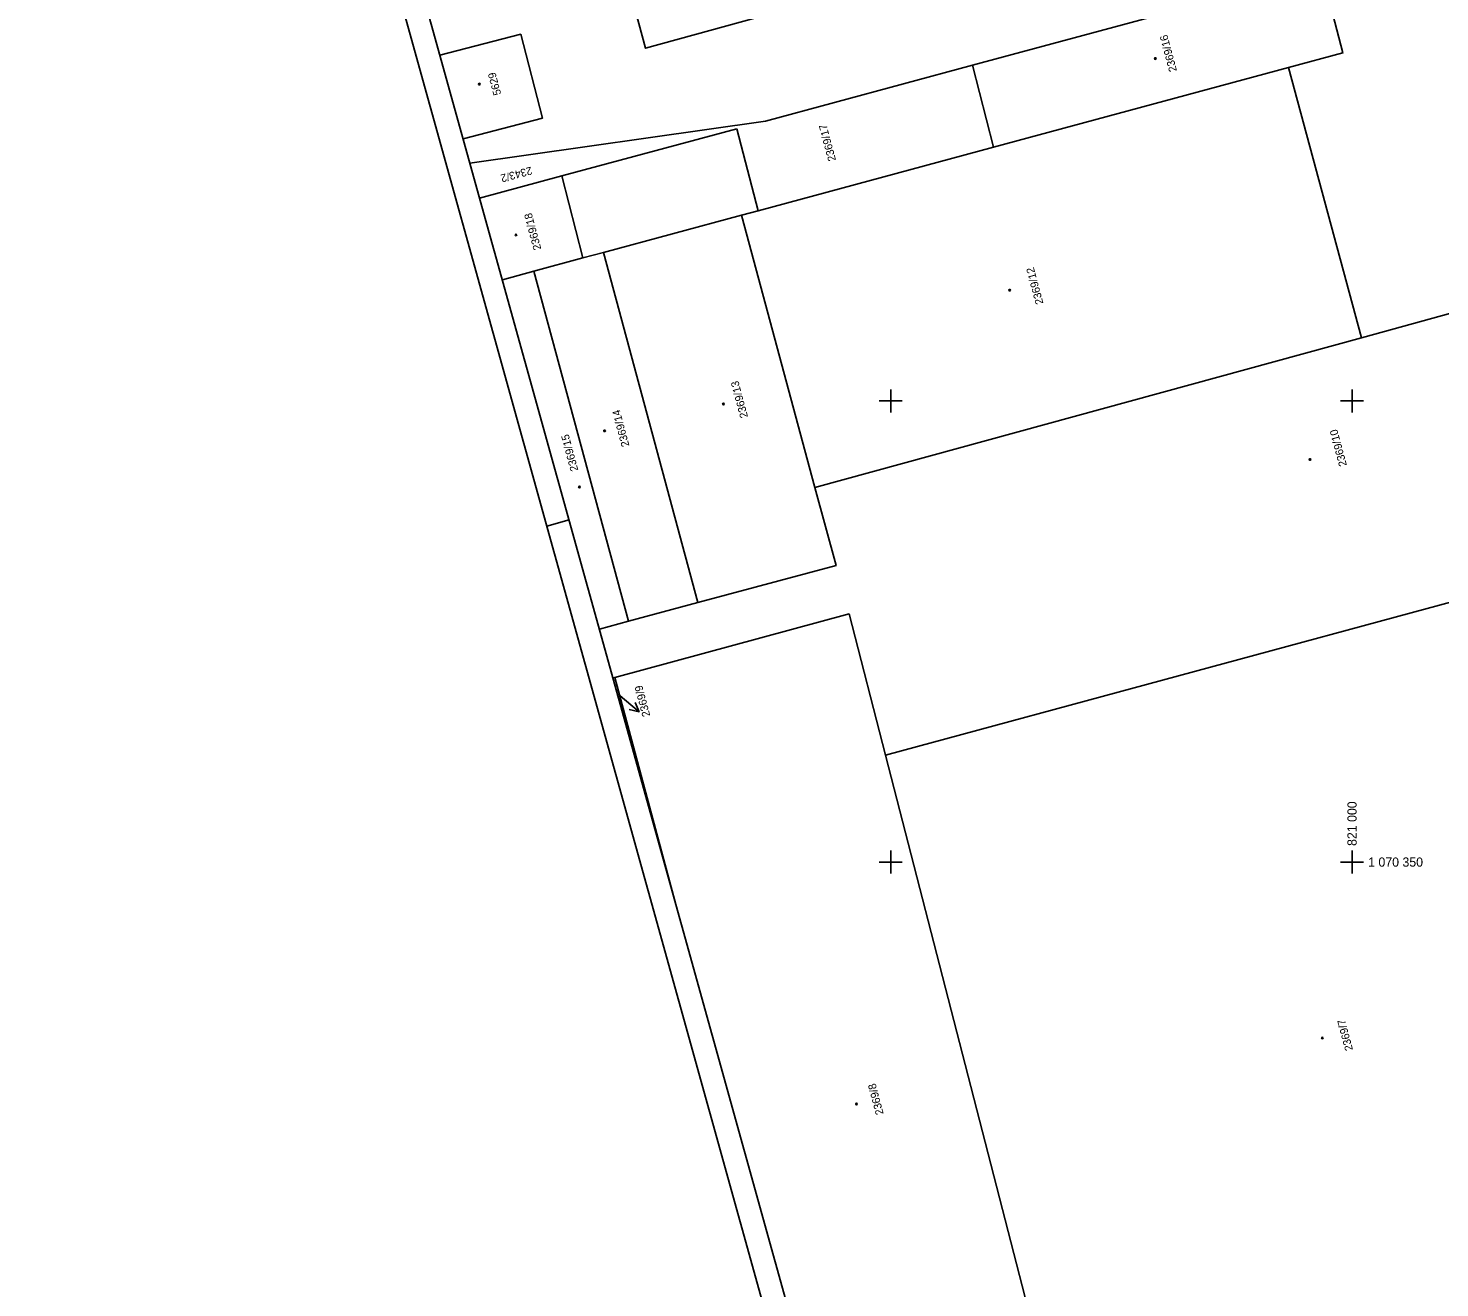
# Model space of a CAD drawing. Extents: x -821172 to -820632, y -1070921 to -1069931.
# Drawn here: x -821143.5 to -820990.5, y -1070396.2 to -1070259.6 of the extents above; entities that cross this region are included whole.
import ezdxf

# ---------------------------------------------------------------- set-up
doc = ezdxf.new("R2010")
doc.units = 0
for name, color, linetype in [('Ram', 7, 'Continuous'), ('Sit', 7, 'Continuous'), ('Vrstva 55', 7, 'Continuous'), ('Vrstva 56', 7, 'Continuous'), ('Vrstva 57', 7, 'Continuous'), ('Vrstva 59', 7, 'Continuous')]:
    doc.layers.add(name, color=color, linetype=linetype)

msp = doc.modelspace()

# ---------------------------------------------------------------- linework, layer by layer
at = {"layer": 'Ram'}
msp.add_line((-821084.88, -1070312.9), (-821087.29, -1070313.57), dxfattribs=at)
for points in [[(-820775.54, -1070880.81), (-820918.62, -1070920.57), (-821143.51, -1070111.23)], [(-820916.88, -1070917.49), (-821140.43, -1070112.97)]]:
    msp.add_lwpolyline(points, dxfattribs=at)
at = {"layer": 'Sit'}
for p, q in [((-821050, -1070298.75), (-821050, -1070300)), ((-821000, -1070298.75), (-821000, -1070300)), ((-821051.25, -1070300), (-821050, -1070300)), ((-821048.75, -1070300), (-821050, -1070300)), ((-821050, -1070301.25), (-821050, -1070300)), ((-821001.25, -1070300), (-821000, -1070300)), ((-820998.75, -1070300), (-821000, -1070300)), ((-821000, -1070301.25), (-821000, -1070300)), ((-821050, -1070348.75), (-821050, -1070350)), ((-821000, -1070348.75), (-821000, -1070350)), ((-821051.25, -1070350), (-821050, -1070350)), ((-821048.75, -1070350), (-821050, -1070350)), ((-821050, -1070351.25), (-821050, -1070350)), ((-821001.25, -1070350), (-821000, -1070350)), ((-820998.75, -1070350), (-821000, -1070350)), ((-821000, -1070351.25), (-821000, -1070350))]:
    msp.add_line(p, q, dxfattribs=at)
at = {"layer": 'Vrstva 55'}
for p, q in [((-821041.15, -1070263.6), (-821063.59, -1070269.66)), ((-821041.15, -1070263.6), (-821038.86, -1070272.49)), ((-821006.88, -1070263.86), (-821038.86, -1070272.49)), ((-821006.88, -1070263.86), (-820998.99, -1070293.15)), ((-821085.66, -1070275.61), (-821066.68, -1070270.49)), ((-821064.39, -1070279.38), (-821066.68, -1070270.49)), ((-821038.86, -1070272.49), (-821064.39, -1070279.38)), ((-821085.66, -1070275.61), (-821083.37, -1070284.5)), ((-821083.37, -1070284.5), (-821088.68, -1070285.94)), ((-821088.68, -1070285.94), (-821078.44, -1070323.89)), ((-820970.82, -1070285.44), (-820998.99, -1070293.15)), ((-820998.99, -1070293.15), (-821058.23, -1070309.37)), ((-820978.59, -1070318.91), (-821050.57, -1070338.41)), ((-821070.91, -1070321.87), (-821078.44, -1070323.89)), ((-821079.93, -1070329.99), (-821073.29, -1070354.59)), ((-821050.57, -1070338.41), (-821028.04, -1070425.85))]:
    msp.add_line(p, q, dxfattribs=at)
for points in [[(-821049.48, -1070244.11), (-821046.85, -1070253.56), (-821076.58, -1070261.77), (-821079.11, -1070252.34), (-821049.48, -1070244.11)], [(-821001.88, -1070258.94), (-821003.37, -1070253.41), (-821041.15, -1070263.6)], [(-821001.88, -1070258.94), (-821000.98, -1070262.27), (-821006.88, -1070263.86)], [(-821098.88, -1070262.51), (-821090.11, -1070260.24), (-821087.76, -1070269.34), (-821096.36, -1070271.58)], [(-821063.59, -1070269.66), (-821095.63, -1070274.21)], [(-821094.57, -1070278.02), (-821085.66, -1070275.61)], [(-821064.39, -1070279.38), (-821066.18, -1070279.87), (-821058.23, -1070309.37)], [(-821083.37, -1070284.5), (-821081.14, -1070283.9), (-821070.91, -1070321.87)], [(-821088.68, -1070285.94), (-821092.11, -1070286.87)], [(-821058.23, -1070309.37), (-821055.94, -1070317.85), (-821070.91, -1070321.87)], [(-821050.57, -1070338.41), (-821054.52, -1070323.09), (-821079.93, -1070329.99)], [(-821078.44, -1070323.89), (-821081.59, -1070324.74)], [(-821079.93, -1070329.99), (-821080.11, -1070330.04)]]:
    msp.add_lwpolyline(points, dxfattribs=at)
at = {"layer": 'Vrstva 56'}
msp.add_line((-821081.14, -1070283.9), (-821066.18, -1070279.87), dxfattribs=at)
at = {"layer": 'Vrstva 57'}
for p, q in [((-821079.54, -1070331.78), (-821077.29, -1070333.72)), ((-821077.29, -1070333.72), (-821077.71, -1070332.7)), ((-821077.29, -1070333.72), (-821078.36, -1070333.45))]:
    msp.add_line(p, q, dxfattribs=at)
at = {"layer": 'Vrstva 59'}
for centre in [(-821021.32, -1070262.88), (-821094.61, -1070265.65), (-821090.62, -1070282), (-821037.11, -1070287.99), (-821068.14, -1070300.34), (-821081.03, -1070303.24), (-821004.55, -1070306.35), (-821083.75, -1070309.33), (-821003.21, -1070369.07), (-821053.72, -1070376.23)]:
    msp.add_circle(centre, 0.0875, dxfattribs=at)

# ---------------------------------------------------------------- texts
at = {"layer": 'Sit'}
msp.add_text('821 000', height=1, rotation=90, dxfattribs=at).set_placement((-820999.5, -1070348.25))
msp.add_text('1 070 350', height=1, dxfattribs=at).set_placement((-820998.25, -1070350.5))
at = {"layer": 'Vrstva 57'}
for s, rotation, p in [('2369/16', 105, (-821018.97, -1070264.2)), ('5629', 105, (-821092.22, -1070266.74)), ('2369/17', 105, (-821055.93, -1070273.89)), ('2343/2', 195, (-821089.01, -1070274.59)), ('2369/18', 105, (-821087.88, -1070283.52)), ('2369/12', 105, (-821033.45, -1070289.41)), ('2369/13', 105, (-821065.47, -1070301.73)), ('2369/14', 105, (-821078.33, -1070304.85)), ('2369/15', 105, (-821083.87, -1070307.51)), ('2369/10', 105, (-821000.55, -1070306.98)), ('2369/9', 105, (-821076.07, -1070334.12)), ('2369/7', 105, (-820999.89, -1070370.34)), ('2369/8', 105, (-821050.77, -1070377.29))]:
    msp.add_text(s, height=0.85, rotation=rotation, dxfattribs=at).set_placement(p)

doc.saveas('drawing.dxf')
